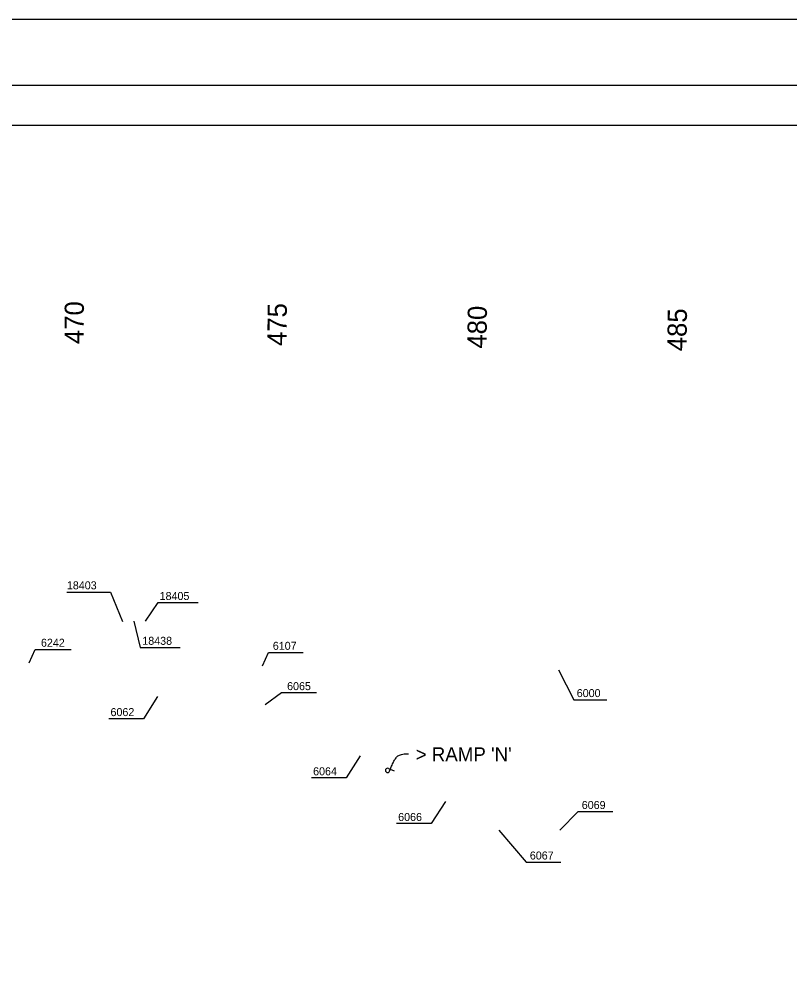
# Model space of a CAD drawing. Extents: x 2150710 to 2158723, y 139737 to 144537.
# Drawn here: x 2154871 to 2156797, y 142137 to 144537 of the extents above; entities that cross this region are included whole.
import ezdxf

# ---------------------------------------------------------------- set-up
doc = ezdxf.new("R2010")
doc.units = 0
for name, color, linetype in [('Default', 7, 'Continuous'), ('PR_Align_2_PI_Curve', 7, 'Continuous'), ('PR_Txt', 7, 'Continuous'), ('SHT_Plot_Shape_Full', 7, 'Continuous'), ('SHT_Plot_Shape_Half', 7, 'Continuous'), ('SHT_Sheet_Border', 7, 'Continuous')]:
    doc.layers.add(name, color=color, linetype=linetype)

# ---------------------------------------------------------------- blocks, each defined once
blk = doc.blocks.new('DWG01015')
at = {"layer": 'Default'}
for p, q in [((0, 0.119), (0.357, 0.119)), ((0.119, 0), (0.119, 0.318))]:
    blk.add_line(p, q, dxfattribs=at)
blk.add_arc((0, 0), 0.119, 90, 0, dxfattribs=at)

msp = doc.modelspace()

# ---------------------------------------------------------------- linework, layer by layer
at = {"layer": 'PR_Align_2_PI_Curve'}
for points in [[(2154989.7, 143105.8), (2155098.4, 143105.8), (2155128.6, 143032.4)], [(2155185.8, 143033.4), (2155218.2, 143079.3), (2155318.2, 143079.3)], [(2155157.2, 143032.6), (2155172.9, 142967.2), (2155272.8, 142967.2)], [(2154895.2, 142928.7), (2154910.6, 142962.5), (2155000.7, 142962.5)], [(2155478.5, 142921), (2155493.9, 142954.8), (2155580.5, 142954.8)], [(2156218.3, 142911.2), (2156257.1, 142836.6), (2156339.6, 142836.6)], [(2155613.4, 142854.1), (2155526.5, 142854.1), (2155485.4, 142824.3)], [(2155216.5, 142844.7), (2155181.1, 142789.2), (2155094.5, 142789.2)], [(2155722.9, 142696.8), (2155687.5, 142641.3), (2155600.9, 142641.3)], [(2155935.6, 142582.6), (2155900.1, 142527.1), (2155813.5, 142527.1)], [(2156221.9, 142511.2), (2156268, 142557.1), (2156354.6, 142557.1)], [(2156069.7, 142510.6), (2156137.9, 142430.9), (2156224.5, 142430.9)]]:
    msp.add_lwpolyline(points, dxfattribs=at)
at = {"layer": 'PR_Txt'}
msp.add_open_spline([(2155801.4, 142671.1), (2155802.9, 142674.4), (2155806.1, 142681.7), (2155810.5, 142689.3), (2155817.2, 142697), (2155824.2, 142700.3), (2155835.3, 142701.7), (2155843.6, 142701.4)], degree=3, dxfattribs=at)
at = {"layer": 'SHT_Plot_Shape_Full'}
msp.add_lwpolyline([(2151522.6, 144537), (2158722.6, 144537), (2158722.6, 139737), (2151522.6, 139737)], close=True, dxfattribs=at)
at = {"layer": 'SHT_Plot_Shape_Half'}
msp.add_lwpolyline([(2151850.1, 144372), (2158650.1, 144372), (2158650.1, 139972), (2151850.1, 139972)], close=True, dxfattribs=at)
at = {"layer": 'SHT_Sheet_Border'}
msp.add_lwpolyline([(2158540.1, 140072), (2152240.1, 140072), (2152240.1, 144272), (2158540.1, 144272)], close=True, dxfattribs=at)

# ---------------------------------------------------------------- block references
at = {"layer": 'PR_Txt', "xscale": 44.094400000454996, "yscale": 44.094400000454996, "rotation": -22.40679487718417}
msp.add_blockref('DWG01015', (2155791.2, 142660.1), dxfattribs=at)

# ---------------------------------------------------------------- texts
at = {"layer": 'PR_Align_2_PI_Curve'}
for s, p in [('18403', (2154989.7, 143112.5)), ('18405', (2155221.5, 143085.9)), ('18438', (2155178.2, 142973.9)), ('6242', (2154924.9, 142969.1)), ('6107', (2155504.4, 142961.4)), ('6065', (2155540.1, 142860.7)), ('6000', (2156264.1, 142843.3)), ('6062', (2155098.7, 142795.8)), ('6064', (2155605.1, 142647.9)), ('6069', (2156276.6, 142563.7)), ('6066', (2155817.7, 142533.7)), ('6067', (2156146.8, 142437.5))]:
    msp.add_text(s, height=20, dxfattribs=at).set_placement(p)
at = {"layer": 'PR_Txt'}
for s, rotation, p in [('470', 89.7178, (2155031.8, 143725.2)), ('475', 89.2432, (2155538.4, 143720.3)), ('480', 89.2432, (2156038.4, 143713.7)), ('485', 89.2432, (2156538.3, 143707.1))]:
    msp.add_text(s, height=48, rotation=rotation, dxfattribs=at).set_placement(p)
msp.add_text("> RAMP 'N'", height=35, dxfattribs=at).set_placement((2155861.3, 142682.8))

doc.saveas('drawing.dxf')
